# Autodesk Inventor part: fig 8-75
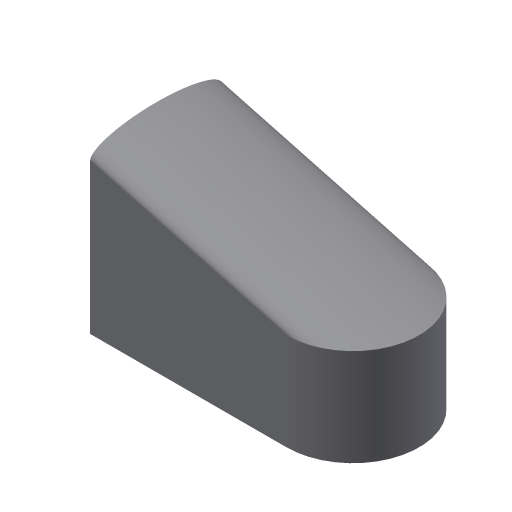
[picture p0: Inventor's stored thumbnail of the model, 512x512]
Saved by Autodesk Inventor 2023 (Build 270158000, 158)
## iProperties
Created: 2002-01
Part Number: fig 8-75
Document SubType Name: Modeling
Designer: ***
Density: 1 g/cm^3
Material: Generic
Appearance: Default
Control State: 0
Master: False
Checked Out: False
Shininess: 77.0
Length Units: 11269
Angle Units: 11279
Time Units: 11290
Mass Units: 11283
Length Display Precision: 3
Angle Display Precision: 2
Density: 0.0
Volumn: 0.0
Area: 0.0
PropertySet Name: Model Information
Author: ***
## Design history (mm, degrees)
sketch "Sketch2"
  geometry: L1 (-36.915, 19.946)-(-36.915, -14.161); L2 (-36.915, -14.161)-(13.729, -14.161); L3 (13.729, 19.946)-(-36.915, 19.946); A1 r 17.054 centre (13.729, 2.893) between (13.729, -14.161) and (13.729, 19.946)
  constraints: 6 end point, 2 point on circle, 2 tangent, 1 centre point, 1 parallel, 1 perpendicular, 1 vertical
extrude "Extrusion2" new body sketch "Sketch2" distance "d6" = 25; taper "d7" = 0 deg
feature "FaceDraft9" dims angle "d15" = 15 deg
body "Solid1"
